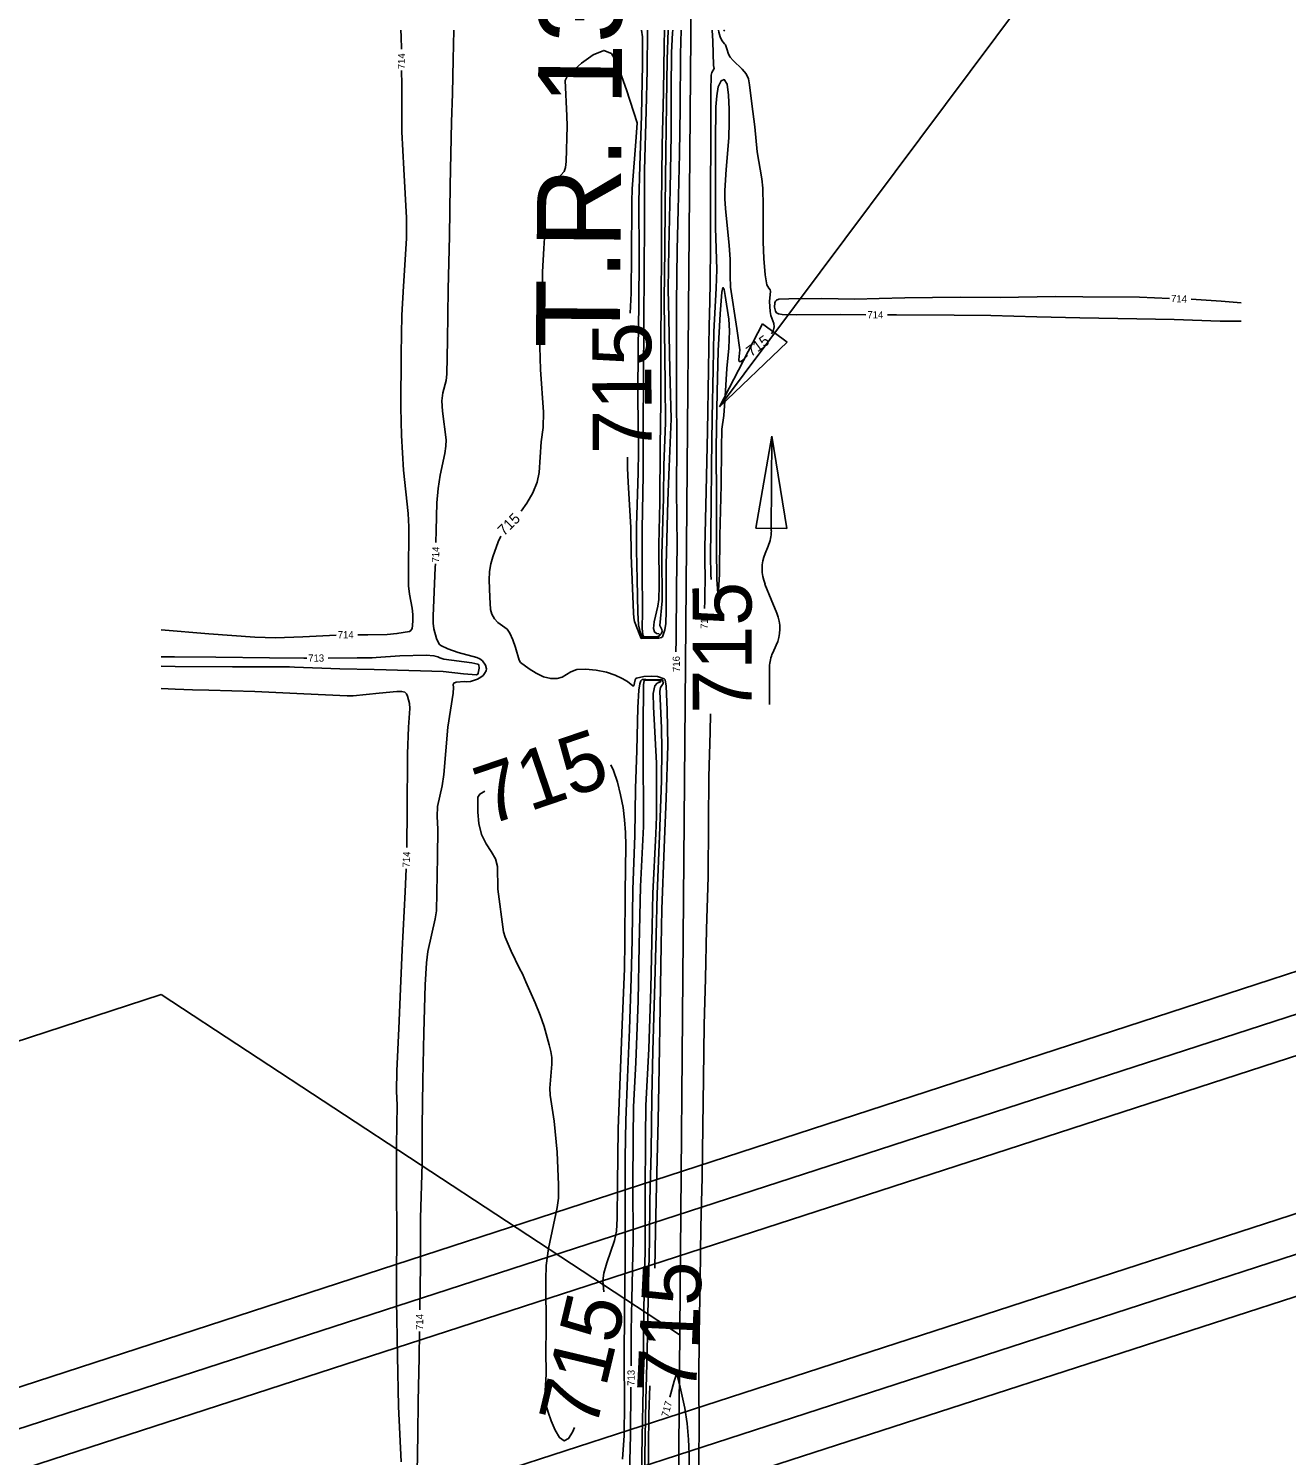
# Model space of a CAD drawing. Extents: x -468556195 to 3353078, y -306091294 to 1252632.
# Drawn here: x 1829375 to 1830079, y 533730 to 534528 of the extents above; entities that cross this region are included whole.
import ezdxf

# ---------------------------------------------------------------- set-up
doc = ezdxf.new("R2010")
doc.units = 0
for name, color, linetype in [('Default', 7, 'Continuous'), ('DT_X_Contour_Minor', 7, 'Continuous'), ('DT_X_Terrain_Boundary', 7, 'Continuous'), ('Level 19', 7, 'Continuous'), ('Level 31', 7, 'Continuous'), ('Level 40', 7, 'Continuous'), ('SC_Shading3', 7, 'Continuous')]:
    doc.layers.add(name, color=color, linetype=linetype)

msp = doc.modelspace()

# ---------------------------------------------------------------- linework, layer by layer
at = {"layer": 'Default'}
for points in [[(1827117.12, 533034.5), (1827123.3, 533015.48), (1834732.36, 535485.81), (1834723.97, 535511.59)], [(1827162.83, 532893.73), (1827168.81, 532875.29), (1833162.58, 534815.33), (1833154.87, 534839.74)]]:
    msp.add_lwpolyline(points, close=True, dxfattribs=at)
at = {"layer": 'DT_X_Contour_Minor'}
for points in [[(1829583.88, 534516.19), (1829583.81, 534523.3), (1829583.51, 534526.91)], [(1829613.15, 534526.9), (1829612.77, 534510.4), (1829612.37, 534491.4), (1829611.9, 534475.36), (1829611.59, 534457.69), (1829611.12, 534439.94), (1829610.72, 534411.93), (1829609.98, 534381.89), (1829609.59, 534353.56), (1829609.31, 534334.49), (1829608.85, 534330.91), (1829607.02, 534324.12), (1829606.53, 534319.63), (1829606.83, 534313.87), (1829608.87, 534297.86), (1829608.8, 534294.28), (1829608.17, 534290.19), (1829605.61, 534278.03), (1829604.41, 534270.51), (1829603.72, 534262.58), (1829603.33, 534247.04), (1829603.17, 534240.35)], [(1829710.25, 534288.16), (1829710.29, 534281.87), (1829710.62, 534274.1), (1829712.2, 534248.74), (1829712.35, 534233.23), (1829713.56, 534201.07), (1829713.79, 534198.2), (1829714.28, 534196.11), (1829717.16, 534188.53), (1829717.99, 534186.75), (1829727.86, 534186.97), (1829729.31, 534187.2), (1829729.94, 534187.67), (1829731.08, 534191.55), (1829731.76, 534195.1), (1829731.93, 534202), (1829731.86, 534227.72), (1829732.83, 534263.61), (1829733.56, 534282.63), (1829734.69, 534309.61), (1829733.99, 534336.75), (1829733.37, 534365.92), (1829733.11, 534382.03), (1829733.47, 534405.08), (1829734.12, 534437.98), (1829734.62, 534468.38), (1829734.63, 534493.72), (1829734.86, 534514.4), (1829735.47, 534525.37), (1829735.61, 534526.86)], [(1829718.06, 534526.87), (1829718.66, 534523.03), (1829718.59, 534507.56), (1829718.2, 534479.09), (1829717.16, 534450.96), (1829716.71, 534431.17), (1829716.73, 534399.99), (1829716.6, 534373.34), (1829716.33, 534349.27), (1829716.09, 534322.11), (1829716.36, 534291.09), (1829716.23, 534279.5), (1829715.38, 534249.43), (1829715.28, 534236.16), (1829715.7, 534219.66), (1829716.12, 534201.29), (1829716.4, 534194.33), (1829717.56, 534189.67), (1829718.79, 534187.18), (1829720.84, 534187.16), (1829724.53, 534187.22), (1829726.41, 534187.46), (1829728.08, 534188.1), (1829729.15, 534189.23), (1829729.62, 534190.55), (1829729.57, 534191.67), (1829728.29, 534193.88), (1829729.58, 534207.69), (1829729.43, 534233.55), (1829730.38, 534265.31), (1829730.67, 534283.59), (1829731.5, 534307.33), (1829731.32, 534329.27), (1829730.98, 534358.98), (1829730.8, 534376.24), (1829731.19, 534404.21), (1829731.35, 534429.02), (1829731.73, 534458.62), (1829732.16, 534485.37), (1829732.54, 534510.49), (1829733.11, 534526.86)], [(1829721.4, 534526.87), (1829721.22, 534504.42), (1829720.78, 534481.78), (1829719.83, 534448.52), (1829719.77, 534419.47), (1829719.65, 534391.86), (1829719.49, 534364.27), (1829719.15, 534331.83), (1829718.99, 534305.14), (1829719, 534278.09), (1829718.5, 534248.1), (1829718.53, 534225.25), (1829718.68, 534201.51), (1829718.52, 534192.54), (1829718.88, 534188.56), (1829719.36, 534187.65), (1829720.35, 534187.54), (1829727.39, 534187.69), (1829728.02, 534187.92), (1829728.39, 534188.34), (1829728.35, 534188.83), (1829727.76, 534189.25), (1829726.59, 534189.57), (1829725.36, 534190.38), (1829724.74, 534192.36), (1829725.16, 534195.94), (1829727.26, 534204.84), (1829727.84, 534208.52), (1829727.96, 534216.37), (1829727.88, 534239.29), (1829728.32, 534262.74), (1829728.54, 534294.2), (1829728.84, 534319.04), (1829728.99, 534350.96), (1829729.03, 534377.97), (1829729.26, 534401.44), (1829729.38, 534429.05), (1829729.65, 534462.37), (1829730.4, 534492.4), (1829730.83, 534518.6), (1829731.03, 534526.86)], [(1829737.37, 534179.3), (1829737.56, 534185.74), (1829737.74, 534215.69), (1829737.96, 534238.59), (1829737.67, 534269.88), (1829737.9, 534296.14), (1829737.65, 534323.69), (1829737.73, 534347.71), (1829737.7, 534373.93), (1829737.99, 534404.13), (1829738.55, 534426.43), (1829739.4, 534457.72), (1829739.65, 534483.22), (1829739.92, 534513.47), (1829740.35, 534526.86)], [(1829757.64, 534526.86), (1829757.9, 534520.75), (1829758.34, 534507.07), (1829758.72, 534505.32), (1829757.38, 534503.15), (1829757.09, 534501.58), (1829756.92, 534492.67), (1829756.83, 534464.41), (1829756.71, 534437.76), (1829756.71, 534407.09), (1829756.56, 534384.84), (1829756.07, 534367.35), (1829755.87, 534362.32), (1829755.56, 534336.87), (1829754.98, 534302.68), (1829754.33, 534269.02), (1829753.54, 534237.38), (1829753.46, 534227.1), (1829753.62, 534223.67), (1829753.47, 534207.65), (1829753.38, 534203.38)], [(1829761.22, 534526.85), (1829761.38, 534525.77), (1829762.12, 534523.08), (1829762.96, 534521.04), (1829764.54, 534519.25), (1829765.12, 534518.65), (1829765.8, 534516.36), (1829766.66, 534513.35), (1829767.63, 534511.69), (1829769.28, 534509.79), (1829774.4, 534505.1), (1829776.62, 534502.46), (1829777.87, 534499.66), (1829778.49, 534496.26), (1829779.77, 534485.71), (1829781.45, 534472.77), (1829782.69, 534458.82), (1829785.46, 534443.66), (1829785.95, 534438.51), (1829786.13, 534428.37), (1829786.17, 534408.45), (1829786.49, 534399.08), (1829787.2, 534390.05), (1829788.25, 534384.36), (1829789.36, 534382.5), (1829790.08, 534381.71), (1829790.18, 534380.94), (1829789.73, 534375.2), (1829790.02, 534369.6), (1829790.46, 534367.24), (1829792.12, 534362.88), (1829792.19, 534360.91), (1829791.64, 534358.57), (1829790.73, 534357.03)], [(1829764.03, 534526.85), (1829764.07, 534526.69), (1829764.56, 534526.61), (1829764.68, 534526.85)], [(1829650.91, 534257.97), (1829654.08, 534262.43), (1829657.33, 534268.18), (1829659.74, 534274.07), (1829660.89, 534279.48), (1829662.11, 534296.57), (1829663.08, 534304.7), (1829663.25, 534313.3), (1829661.64, 534337.05), (1829661.26, 534349.86), (1829661.96, 534358.24), (1829662.57, 534366.57), (1829662.62, 534379.18), (1829662.75, 534391.7), (1829663.48, 534404.83), (1829664, 534413.69), (1829663.99, 534421.45), (1829663.8, 534428.88), (1829664.19, 534432.65), (1829665.45, 534436.39), (1829667.83, 534440), (1829674.81, 534447.87), (1829675.58, 534450.04), (1829675.91, 534453.46), (1829676.48, 534473.1), (1829676.38, 534478.89), (1829675.47, 534498.77), (1829676.49, 534500.88), (1829679.39, 534503.73), (1829684.62, 534508.38), (1829691.01, 534513.11), (1829696.97, 534515.5), (1829701.3, 534513.78), (1829704.38, 534508.64), (1829709.64, 534493.47), (1829715.61, 534475), (1829715.2, 534467.07), (1829712.97, 534438.13), (1829712.66, 534431.09), (1829712.72, 534427.8), (1829712.58, 534402.18), (1829712.42, 534379.86), (1829711.78, 534368.67)], [(1829559.48, 534188.83), (1829565.19, 534188.83), (1829575.84, 534188.85), (1829581.37, 534189.4), (1829588.36, 534190.62), (1829589.24, 534191.18), (1829589.82, 534192.2), (1829590.14, 534193.98), (1829590.28, 534196.67), (1829590.19, 534200.04), (1829589.83, 534203.71), (1829588.48, 534211.48), (1829587.94, 534216.2), (1829587.77, 534221.85), (1829588.11, 534249.22), (1829587.73, 534256.52), (1829585.11, 534280.78), (1829583.96, 534300.15), (1829583.6, 534315.81), (1829583.77, 534345.91), (1829584.04, 534367.55), (1829584.99, 534383.72), (1829586.69, 534410.32), (1829586.7, 534421.81), (1829585.19, 534449.18), (1829584.15, 534470.02), (1829584.08, 534496.48), (1829584, 534504.19)], [(1829777.31, 534344.89), (1829775.22, 534342.63), (1829773.78, 534341.66), (1829772.8, 534341.56), (1829772.48, 534342.52), (1829773.04, 534348.08), (1829771.35, 534360.04), (1829767.8, 534383.11), (1829767.61, 534389.44), (1829767.74, 534398.7), (1829767.14, 534406.41), (1829765.05, 534427.1), (1829764.71, 534432.46), (1829764.68, 534437.13), (1829765.49, 534449.01), (1829766.97, 534466.64), (1829767.13, 534475.45), (1829767.09, 534482.68), (1829766.77, 534490.51), (1829765.92, 534496.62), (1829764.4, 534499.2), (1829762.61, 534498.49), (1829761.06, 534495.22), (1829760.15, 534490.13), (1829759.76, 534483.9), (1829759.56, 534464.09), (1829759.51, 534435.96), (1829759.57, 534416.39), (1829760.15, 534393.09), (1829759.93, 534382.51), (1829758.55, 534358.07), (1829758.11, 534337.34), (1829757.59, 534310.05), (1829757.22, 534283.02), (1829757.09, 534261.14), (1829756.67, 534232.84), (1829756.89, 534222.39), (1829757.08, 534219.7)], [(1829763.05, 534303.79), (1829764.06, 534311.42), (1829764.83, 534322.14), (1829765.84, 534337.75), (1829767.03, 534348.96), (1829767.4, 534358.64), (1829767.01, 534365.3), (1829764.98, 534378.45), (1829764.31, 534381.82), (1829763.63, 534382.91), (1829763.04, 534380.41), (1829762.03, 534368.18), (1829760.94, 534347.63), (1829760.38, 534324.65), (1829759.84, 534293.55), (1829760.08, 534263.46), (1829759.98, 534236.76), (1829760.25, 534219.83), (1829760.82, 534211.83), (1829761.15, 534213.51), (1829761.64, 534222.74), (1829761.98, 534244.09), (1829762.68, 534272.38), (1829762.92, 534293.26), (1829763.05, 534303.79)], [(1830013.35, 534376.84), (1829996.49, 534377.48), (1829964.92, 534377.75), (1829949.65, 534378.01), (1829918.7, 534377.36), (1829896.22, 534377.47), (1829865.37, 534377.15), (1829850.95, 534376.83), (1829837.3, 534376.4), (1829818.68, 534376.74), (1829800.48, 534376.7), (1829794.8, 534376.34), (1829793.61, 534375.92), (1829792.95, 534375.24), (1829792.63, 534374.34), (1829792.55, 534372.01), (1829793, 534369.66), (1829793.54, 534368.82), (1829794.66, 534368.22), (1829796.74, 534367.86), (1829804.51, 534367.62), (1829829.25, 534367.78), (1829843.6, 534367.73)], [(1830053.34, 534374.32), (1830042.23, 534375.37), (1830025.34, 534376.39)], [(1829855.6, 534367.69), (1829860.63, 534367.67), (1829892.89, 534367.54), (1829913.4, 534367.38), (1829939.16, 534366.5), (1829963.25, 534366), (1829994.96, 534365.47), (1830015.86, 534365.09), (1830041.64, 534364.18), (1830053.41, 534364.18)], [(1829725.52, 533834.72), (1829725.99, 533855.26), (1829726.53, 533880.95), (1829727.45, 533917.25), (1829727.9, 533946.78), (1829728.6, 533980.7), (1829729.06, 534015.31), (1829729.51, 534035.35), (1829730.78, 534069.57), (1829731.85, 534097.41), (1829732.92, 534126.91), (1829732.46, 534146.86), (1829731.85, 534159.96), (1829731.29, 534163.55), (1829730.84, 534164.14), (1829727.11, 534165.38), (1829723.74, 534165.63), (1829719.46, 534165.43), (1829715.28, 534164.55), (1829714.88, 534164.28), (1829714.6, 534163.6), (1829713.82, 534160.21), (1829713.22, 534160.28), (1829710.25, 534162.6), (1829707.36, 534164.37), (1829703.44, 534166.2), (1829698.49, 534167.84), (1829692.69, 534169.04), (1829686.85, 534169.6), (1829681.91, 534169.32), (1829678.53, 534168.14), (1829673.81, 534165.06), (1829670.89, 534164.27), (1829667.35, 534164.33), (1829663.35, 534165.35), (1829659.14, 534167.29), (1829655.23, 534169.65), (1829650.51, 534173.27), (1829649.63, 534174.58), (1829647.58, 534181.66), (1829646.14, 534186.03), (1829644.56, 534189.77), (1829642.98, 534191.94), (1829637.71, 534195.63), (1829635.9, 534197.75), (1829634.51, 534200.23), (1829633.75, 534202.95), (1829633.3, 534209.83), (1829633, 534219.28), (1829633.18, 534224.08), (1829633.83, 534228.4), (1829634.91, 534232.42), (1829638.02, 534240.73), (1829639.49, 534243.89)], [(1829602.88, 534228.36), (1829602.83, 534226.31), (1829601.6, 534199.19), (1829601.71, 534195.29), (1829602.09, 534192.11), (1829603.51, 534186.68), (1829605.04, 534183.52), (1829605.99, 534182.71), (1829609.75, 534180.92), (1829615.61, 534178.78), (1829625.99, 534176.16), (1829627.79, 534175.24), (1829629.2, 534174.18), (1829630.86, 534171.86), (1829631.49, 534169.77), (1829631.26, 534168.67), (1829630.42, 534167.15), (1829629.55, 534166.1), (1829628.22, 534165.02), (1829626.41, 534164.05), (1829622.52, 534162.72), (1829620.16, 534162.46), (1829619.13, 534162.57), (1829614.48, 534162.26), (1829613.18, 534161.81), (1829612.83, 534160.94), (1829612.96, 534159.22), (1829612.9, 534156.18), (1829609.88, 534137.13), (1829607.69, 534110.67), (1829606.64, 534104.31), (1829604.01, 534092.75), (1829603.92, 534087.24), (1829604.23, 534080.12), (1829604.15, 534064.65), (1829603.5, 534034.39), (1829602.85, 534029.96), (1829598.7, 534011.7), (1829597.88, 534005.29), (1829597.26, 533993.13), (1829596.49, 533966.46), (1829595.95, 533939.51), (1829595.52, 533913.81), (1829595.41, 533893.18), (1829594.52, 533862.67), (1829594.47, 533836.33), (1829594.15, 533811.3)], [(1829449.6, 534191.62), (1829476.21, 534189.27), (1829501.98, 534187.36), (1829513.53, 534187.08), (1829528.81, 534187.67), (1829547.48, 534188.57)], [(1829449.56, 534171.19), (1829457.36, 534171.13), (1829489.4, 534170.94), (1829521.33, 534170.79), (1829524.05, 534170.67), (1829549.52, 534169.78), (1829568.67, 534169.39), (1829575.32, 534169.25), (1829607.25, 534168.26), (1829618.55, 534166.96), (1829625.89, 534166.37), (1829626.53, 534166.72), (1829626.84, 534167.38), (1829627.31, 534170.06), (1829627.17, 534171.98), (1829626.65, 534172.39), (1829623.17, 534173.02), (1829607.55, 534175.2), (1829605.37, 534175.98), (1829604.28, 534176.53), (1829602.04, 534177.06), (1829597.71, 534177.37), (1829583, 534177.03), (1829569.84, 534176.06), (1829567.55, 534175.83), (1829559.15, 534175.84), (1829542.99, 534175.79)], [(1829530.99, 534175.75), (1829529.32, 534175.75), (1829510.21, 534175.85), (1829480.06, 534176.18), (1829457.1, 534176.39), (1829449.57, 534176.39)], [(1829719.64, 533696.58), (1829719.99, 533729.95), (1829720.6, 533760.75), (1829721.33, 533788), (1829721.83, 533817.57), (1829722.56, 533849.85), (1829722.83, 533872.21), (1829723.51, 533899.87), (1829723.91, 533930.08), (1829724.45, 533956.07), (1829725.44, 533987.6), (1829726.25, 534021.04), (1829726.85, 534043.71), (1829728.18, 534076.45), (1829729.37, 534107.09), (1829729.53, 534124.74), (1829729.29, 534136.47), (1829728.36, 534157.27), (1829728.77, 534159.34), (1829730.27, 534161.57), (1829730.05, 534163.24), (1829729.67, 534163.62), (1829728.51, 534163.62), (1829720.58, 534163.73), (1829718.55, 534163.74), (1829717.83, 534163.11), (1829717.15, 534161.28), (1829716.65, 534157.84), (1829716.14, 534148.14), (1829715.53, 534124.13), (1829714.74, 534102.91), (1829714.35, 534076.64), (1829713.23, 534046.39), (1829712.94, 534018.21), (1829712.42, 533996.79), (1829711.45, 533968.06), (1829710.28, 533941.29), (1829709.35, 533917.3), (1829709.06, 533896.28), (1829708.91, 533867.4), (1829708.97, 533838.8), (1829708.61, 533810.91)], [(1829712.29, 533780.09), (1829712.35, 533799.37), (1829712.75, 533817.33), (1829713.36, 533850.68), (1829713.25, 533881.26), (1829713.4, 533907.54), (1829713.66, 533924.82), (1829714.86, 533949.66), (1829716.16, 533984.03), (1829716.89, 534015.08), (1829717.57, 534048.05), (1829719.24, 534081.5), (1829719.24, 534090.04), (1829719.03, 534119.44), (1829719.07, 534136.49), (1829719.15, 534160.97), (1829719.58, 534163.08), (1829720.14, 534163.33), (1829727.32, 534163.21), (1829728.95, 534163.05), (1829729, 534162.78), (1829728.79, 534162.44), (1829726.89, 534161.8), (1829725.57, 534160.21), (1829724.71, 534155.99), (1829724.73, 534148.41), (1829726.58, 534117.04), (1829726.44, 534087.24), (1829726.04, 534077.47), (1829724.41, 534044.39), (1829724, 534025.7), (1829723.3, 533990.92), (1829722.23, 533957.22), (1829720.62, 533925.5), (1829720.41, 533907.93), (1829720.2, 533875.83), (1829720.1, 533844.61), (1829719.43, 533812), (1829719.17, 533796.8), (1829719, 533767.43), (1829718.54, 533740.23), (1829717.94, 533708.57)], [(1829586.9, 534069.88), (1829586.96, 534071.78), (1829587.16, 534089.44), (1829587.21, 534122.25), (1829587.93, 534137.05), (1829588.61, 534147.47), (1829588.47, 534150.33), (1829587.31, 534154.54), (1829586.81, 534155.75), (1829585.83, 534156.66), (1829584.08, 534157.1), (1829581.26, 534157.11), (1829571.48, 534156.14), (1829556.95, 534154.59), (1829553.55, 534154.58), (1829529.35, 534155.78), (1829501.93, 534157.01), (1829476.15, 534157.78), (1829467.04, 534158.01), (1829457.45, 534158.42), (1829449.54, 534158.66)], [(1829756.67, 534144.54), (1829756.5, 534134.37), (1829755.72, 534109.35), (1829755.5, 534083.68), (1829755.45, 534053.48), (1829754.51, 534024.27), (1829753.96, 533996.55), (1829753.23, 533970.63), (1829752.71, 533940.71), (1829752.42, 533914.12), (1829752.02, 533885.42), (1829751.34, 533857.54), (1829750.88, 533827.88), (1829750.31, 533797.97), (1829750.19, 533770.98), (1829750.3, 533744.67), (1829749.96, 533714.87)], [(1829697.06, 533821.34), (1829696.49, 533827.5), (1829697.09, 533831.93), (1829698.78, 533837.61), (1829702.97, 533850.11), (1829704.07, 533855.39), (1829704.51, 533862.45), (1829704.65, 533881.72), (1829705, 533912.6), (1829706.2, 533941.88), (1829707.38, 533970.76), (1829708.57, 534002.13), (1829708.86, 534016.79), (1829708.89, 534044.73), (1829709.35, 534071.04), (1829709.19, 534078.24), (1829708.7, 534085.32), (1829707.81, 534092.29), (1829706.45, 534099.35), (1829704.61, 534106.46), (1829702.46, 534112.82), (1829700.88, 534116.06)], [(1829630.44, 534101.28), (1829627.69, 534099.74), (1829626.67, 534097.95), (1829626.53, 534094.82), (1829626.6, 534089.64), (1829627.14, 534083.3), (1829628.59, 534077.07), (1829631.18, 534071.91), (1829634.15, 534067.55), (1829636.5, 534063.45), (1829637.53, 534059.16), (1829637.76, 534046.47), (1829640.95, 534022.76), (1829641.92, 534019.62), (1829645.19, 534011.9), (1829649.97, 534002.16), (1829651.58, 533999.29), (1829653.42, 533994.76), (1829658.66, 533982.98), (1829661.47, 533976.07), (1829663.69, 533969.71), (1829666.53, 533959.52), (1829667.41, 533955.74), (1829667.93, 533952.34), (1829668, 533948.69), (1829666.79, 533935.24), (1829666.98, 533931.42), (1829669.29, 533916.87), (1829670.9, 533899.55), (1829671.68, 533881.31), (1829671.72, 533873.78), (1829670.89, 533868.63), (1829666.17, 533845.56), (1829664.89, 533836.19), (1829664.63, 533828.31), (1829664.85, 533799.87), (1829664.54, 533788.63), (1829664.84, 533775.36), (1829664.06, 533762.81), (1829664.67, 533758.57), (1829665.9, 533754.09), (1829667.67, 533749.24), (1829669.87, 533744.14), (1829672.33, 533739.93), (1829674.89, 533738.03), (1829677.37, 533739.38), (1829679.62, 533743.02), (1829680.65, 533745.56)], [(1829583.81, 533726.32), (1829582.3, 533757.27), (1829581.78, 533785.66), (1829581.07, 533816.53), (1829581.12, 533829.1), (1829581.35, 533853.76), (1829581.17, 533879.21), (1829581.07, 533903.35), (1829581.47, 533925.68), (1829581.14, 533933.51), (1829581.34, 533944.94), (1829582.5, 533968.61), (1829583.52, 533995.21), (1829584.26, 534012.62), (1829586.06, 534045.11), (1829586.49, 534057.88)], [(1829708.61, 533810.91), (1829708.5, 533784.03), (1829708.57, 533758.91), (1829708.39, 533741.08), (1829707.56, 533727.79)], [(1829593.99, 533799.3), (1829593.79, 533784.7), (1829593.29, 533760.23), (1829593.13, 533741.62), (1829592.52, 533709.77)], [(1829737.49, 533774.89), (1829736.34, 533771.38), (1829733.96, 533762.48)], [(1829744.81, 533720.78), (1829744.71, 533730.85), (1829744.39, 533738.93), (1829743.63, 533747.79), (1829742.32, 533756.45), (1829739.42, 533769.86), (1829738.07, 533774.82), (1829737.79, 533775.18), (1829737.49, 533774.89)], [(1829711.17, 533713.12), (1829711.9, 533741.05), (1829712.23, 533768.09)], [(1829721.81, 533716.38), (1829722.15, 533752.87), (1829722.84, 533768.87)]]:
    msp.add_lwpolyline(points, dxfattribs=at)
at = {"layer": 'DT_X_Terrain_Boundary'}
msp.add_line((1829737.27, 533545.36), (1829751.6, 535211.12), dxfattribs=at)
at = {"layer": 'Level 31'}
for p, q in [((1829782.1, 534248.31), (1829790.98, 534299.83)), ((1829790.69, 534246.88), (1829790.98, 534299.83)), ((1829790.98, 534299.83), (1829799.27, 534248.21)), ((1829799.27, 534248.21), (1829782.1, 534248.31)), ((1829788.97, 534238.34), (1829787.25, 534234.25)), ((1829787.15, 534217.15), (1829790.65, 534208.51)), ((1829790.65, 534208.51), (1829793.81, 534200.84)), ((1829793.41, 534182.92), (1829791.46, 534178.7)), ((1829789.58, 534149.84), (1829789.69, 534170.76))]:
    msp.add_line(p, q, dxfattribs=at)
for centre, radius, start, end in [((1829768.3, 534247), 22.4, 337.3227, 359.68272), ((1829807.91, 534225.59), 22.4, 157.28387, 202.12773), ((1829773.08, 534192.35), 22.4, 335.15003, 22.25849), ((1829808.89, 534170.67), 19.2, 155.19991, 179.68272)]:
    msp.add_arc(centre, radius, start, end, dxfattribs=at)
at = {"layer": 'Level 40'}
for p, q in [((1829761.75, 534316.25), (1829785.75, 534362.7)), ((1829785.75, 534362.7), (1829799.51, 534352.4)), ((1829799.51, 534352.4), (1829761.75, 534316.25)), ((1828661.9, 533731.83), (1829449.65, 533987.58)), ((1829449.65, 533987.58), (1829739.22, 533797.46))]:
    msp.add_line(p, q, dxfattribs=at)
msp.add_lwpolyline([(1829761.74, 534316.26), (1829930.04, 534541.31), (1830001.37, 534564.47)], dxfattribs=at)
at = {"layer": 'SC_Shading3'}
for points in [[(1827130.09, 532994.55), (1827117.12, 533034.5), (1834723.97, 535511.59), (1834739.18, 535464.89)], [(1827156.03, 532914.66), (1827168.81, 532875.29), (1833162.58, 534815.33), (1833148.11, 534860.04)]]:
    msp.add_lwpolyline(points, close=True, dxfattribs=at)

# ---------------------------------------------------------------- texts
at = {"layer": 'Level 19'}
for s, height, rotation, p in [('714', 4, 90.59609, (1829585.99, 534505)), ('714', 4, 357.83506, (1830014.06, 534374.81)), ('714', 4, 359.80031, (1829844.38, 534365.73)), ('715', 33, 90.25231, (1829723.86, 534290.03)), ('715', 6, 36.21666, (1829779.41, 534344.01)), ('715', 6, 44.24953, (1829641.22, 534243.81)), ('714', 4, 88.61938, (1829604.9, 534229.1)), ('715', 33, 90.14918, (1829779.8, 534144.73)), ('716', 4, 88.83711, (1829755.15, 534191.99)), ('714', 4, 0.07448, (1829548.27, 534186.81)), ('713', 4, 0.18335, (1829531.77, 534173.76)), ('716', 4, 90.91694, (1829739.66, 534167.98)), ('715', 33, 18.78156, (1829632.22, 534082.01)), ('714', 4, 88.05215, (1829588.52, 534058.6)), ('715', 33, 87.2672, (1829748.52, 533764.23)), ('715', 33, 76.62165, (1829692.5, 533743.62)), ('714', 4, 89.22099, (1829596, 533800.06)), ('713', 4, 89.81113, (1829714.25, 533768.85)), ('717', 4, 74.99444, (1829732.97, 533751.09))]:
    msp.add_text(s, height=height, rotation=rotation, dxfattribs=at).set_placement(p)
at = {"layer": 'Level 40'}
msp.add_text('T.R. 139', height=46.8, rotation=89.52618, dxfattribs=at).set_placement((1829705.87, 534349.01))

doc.saveas('drawing.dxf')
